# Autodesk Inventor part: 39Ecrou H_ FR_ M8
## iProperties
Created: 2011-01
Part Number: 39Ecrou H_ FR_ M8
Document SubType Name: Modeling
Designer: eric
Density: 1 g/cm^3
Mass: 0.816097 g
Surface Area: 6.75325 cm^2
Volume: 0.816097 cm^3
Author: eric
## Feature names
1. Base1
